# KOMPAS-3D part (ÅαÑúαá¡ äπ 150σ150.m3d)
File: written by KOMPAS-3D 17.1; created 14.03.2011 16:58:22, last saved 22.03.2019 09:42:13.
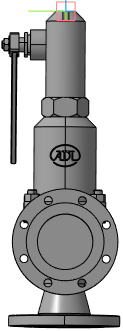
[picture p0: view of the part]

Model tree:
1. Плоскость XY
2. Плоскость ZX
3. Плоскость ZY
4. Ось X
5. Ось Y
6. Ось Z
7. Начало координат
8. Операция без истории:2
